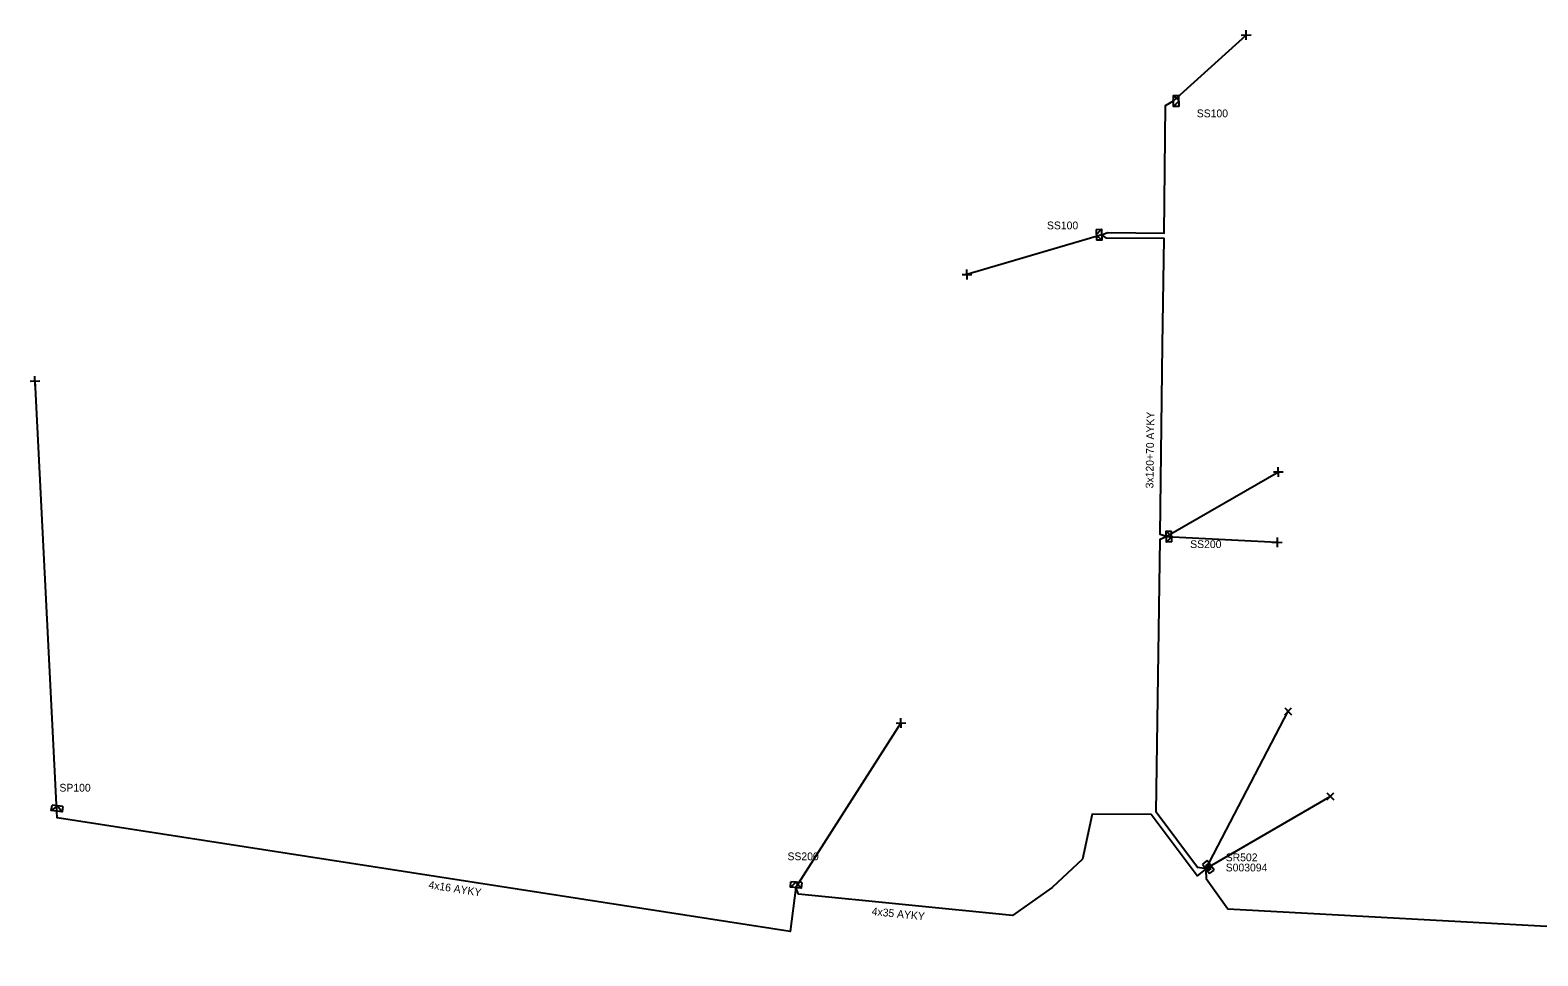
# Model space of a CAD drawing. Extents: x -762894 to -762498, y -1152897 to -1152214.
# Drawn here: x -762894 to -762701.3, y -1152896.3 to -1152777.9 of the extents above; entities that cross this region are included whole.
import ezdxf

# ---------------------------------------------------------------- set-up
doc = ezdxf.new("R2010")
doc.units = 0
for name, color, linetype in [('Vrstva 28', 7, 'Continuous'), ('Vrstva 29', 7, 'Continuous'), ('Vrstva 30', 7, 'Continuous'), ('Vrstva 31', 7, 'Continuous'), ('Vrstva 33', 7, 'Continuous'), ('Vrstva 34', 7, 'Continuous'), ('Vrstva 5', 7, 'Continuous'), ('Vrstva 52', 7, 'Continuous'), ('Vrstva 54', 7, 'Continuous'), ('Vrstva 59', 7, 'Continuous'), ('Vrstva 6', 7, 'Continuous')]:
    doc.layers.add(name, color=color, linetype=linetype)

msp = doc.modelspace()

# ---------------------------------------------------------------- linework, layer by layer
at = {"layer": 'Vrstva 28'}
for points in [[(-762743.546, -1152884.1), (-762744.145, -1152884.551)], [(-762742.643, -1152885.298), (-762743.546, -1152884.1)], [(-762744.145, -1152884.551), (-762743.242, -1152885.749)], [(-762743.466, -1152884.52), (-762743.768, -1152884.747)], [(-762743.768, -1152884.747), (-762743.32, -1152885.342)], [(-762743.475, -1152884.586), (-762743.702, -1152884.757)], [(-762743.702, -1152884.757), (-762743.311, -1152885.276)], [(-762743.485, -1152884.652), (-762743.635, -1152884.766)], [(-762743.635, -1152884.766), (-762743.301, -1152885.209)], [(-762743.494, -1152884.718), (-762743.569, -1152884.775)], [(-762743.569, -1152884.775), (-762743.292, -1152885.143)], [(-762743.279, -1152885.082), (-762743.507, -1152884.78)], [(-762743.217, -1152885.086), (-762743.494, -1152884.718)], [(-762743.15, -1152885.096), (-762743.485, -1152884.652)], [(-762743.084, -1152885.105), (-762743.475, -1152884.586)], [(-762743.018, -1152885.114), (-762743.466, -1152884.52)], [(-762743.32, -1152885.342), (-762743.018, -1152885.114)], [(-762743.311, -1152885.276), (-762743.084, -1152885.105)], [(-762743.301, -1152885.209), (-762743.15, -1152885.096)], [(-762743.292, -1152885.143), (-762743.217, -1152885.086)], [(-762743.242, -1152885.749), (-762742.643, -1152885.298)]]:
    msp.add_lwpolyline(points, dxfattribs=at)
at = {"layer": 'Vrstva 31'}
for points in [[(-762747.127, -1152787.621), (-762747.827, -1152787.633), (-762747.852, -1152786.233), (-762747.152, -1152786.221)], [(-762747.14, -1152786.921), (-762747.852, -1152786.233)], [(-762747.14, -1152786.921), (-762747.827, -1152787.633)], [(-762747.127, -1152787.621), (-762747.152, -1152786.221)], [(-762757.733, -1152803.359), (-762757.033, -1152803.347), (-762757.008, -1152804.747), (-762757.708, -1152804.759)], [(-762757.733, -1152803.359), (-762757.708, -1152804.759)], [(-762757.72, -1152804.059), (-762757.033, -1152803.347)], [(-762757.72, -1152804.059), (-762757.008, -1152804.747)], [(-762748.057, -1152843.341), (-762748.757, -1152843.353), (-762748.782, -1152841.953), (-762748.082, -1152841.941)], [(-762748.07, -1152842.641), (-762748.782, -1152841.953)], [(-762748.07, -1152842.641), (-762748.757, -1152843.353)], [(-762748.057, -1152843.341), (-762748.082, -1152841.941)], [(-762889.816, -1152877.185), (-762889.914, -1152877.878), (-762891.3, -1152877.683), (-762891.203, -1152876.99)], [(-762890.51, -1152877.087), (-762891.3, -1152877.683)], [(-762889.816, -1152877.185), (-762891.203, -1152876.99)], [(-762890.51, -1152877.087), (-762889.914, -1152877.878)], [(-762795.368, -1152886.914), (-762795.429, -1152887.611), (-762796.824, -1152887.489), (-762796.763, -1152886.792)], [(-762796.066, -1152886.853), (-762796.824, -1152887.489)], [(-762795.368, -1152886.914), (-762796.763, -1152886.792)], [(-762796.066, -1152886.853), (-762795.429, -1152887.611)]]:
    msp.add_lwpolyline(points, dxfattribs=at)
at = {"layer": 'Vrstva 34'}
for points in [[(-762738.549, -1152779.125), (-762738.571, -1152777.875)], [(-762739.185, -1152778.511), (-762737.935, -1152778.489)], [(-762774.239, -1152809.755), (-762774.261, -1152808.505)], [(-762774.875, -1152809.141), (-762773.625, -1152809.119)], [(-762893.369, -1152823.375), (-762893.391, -1152822.125)], [(-762894.005, -1152822.761), (-762892.755, -1152822.739)], [(-762734.429, -1152835.005), (-762734.451, -1152833.755)], [(-762735.065, -1152834.391), (-762733.815, -1152834.369)], [(-762735.185, -1152843.391), (-762733.935, -1152843.369)], [(-762734.549, -1152844.005), (-762734.571, -1152842.755)], [(-762733.632, -1152864.558), (-762732.748, -1152865.442)], [(-762733.632, -1152865.442), (-762732.748, -1152864.558)], [(-762783.315, -1152866.511), (-762782.065, -1152866.489)], [(-762782.679, -1152867.125), (-762782.701, -1152865.875)], [(-762728.252, -1152875.438), (-762727.368, -1152876.322)], [(-762728.252, -1152876.322), (-762727.368, -1152875.438)]]:
    msp.add_lwpolyline(points, dxfattribs=at)
at = {"layer": 'Vrstva 5'}
for points in [[(-762743.88, -1152885.12), (-762744.79, -1152884.97), (-762750.07, -1152877.92), (-762749.53, -1152843), (-762748.77, -1152842.65), (-762749.56, -1152842.38), (-762749.24, -1152818.11), (-762749.04, -1152804.54), (-762756.4, -1152804.49), (-762757.02, -1152804.05), (-762756.27, -1152803.74), (-762749.04, -1152803.83), (-762748.86, -1152787.5), (-762747.84, -1152786.93)], [(-762743.72, -1152885.33), (-762743.69, -1152886.39), (-762740.9, -1152890.25), (-762695.44, -1152892.73), (-762694.97, -1152892.29), (-762694.69, -1152892.8), (-762631.53, -1152896.28), (-762630.13, -1152859.24), (-762646.31, -1152858.66), (-762650.77, -1152870.2), (-762650.83, -1152869.13), (-762646.58, -1152858.04), (-762632.87, -1152850.42)], [(-762743.8, -1152885.22), (-762744.82, -1152886.04), (-762750.68, -1152878.19), (-762758.26, -1152878.14), (-762759.5, -1152883.91), (-762763.36, -1152887.55), (-762768.41, -1152891.1), (-762795.77, -1152888.39), (-762796.13, -1152887.55)]]:
    msp.add_lwpolyline(points, dxfattribs=at)
at = {"layer": 'Vrstva 52'}
msp.add_lwpolyline([(-762796.13, -1152887.55), (-762796.84, -1152893.18), (-762890.57, -1152878.63), (-762890.61, -1152877.79)], dxfattribs=at)
at = {"layer": 'Vrstva 59'}
for points in [[(-762747.84, -1152786.93), (-762738.56, -1152778.5)], [(-762757.02, -1152804.05), (-762774.25, -1152809.13)], [(-762890.61, -1152877.79), (-762893.38, -1152822.75)], [(-762748.77, -1152842.65), (-762734.44, -1152834.38)], [(-762748.77, -1152842.65), (-762734.56, -1152843.38)], [(-762796.13, -1152887.55), (-762782.69, -1152866.5)], [(-762743.24, -1152884.28), (-762733.19, -1152865)], [(-762742.93, -1152884.7), (-762727.81, -1152875.88)]]:
    msp.add_lwpolyline(points, dxfattribs=at)

# ---------------------------------------------------------------- texts
at = {"layer": 'Vrstva 29'}
msp.add_text('S003094', height=0.9943, dxfattribs=at).set_placement((-762741.17, -1152885.48))
at = {"layer": 'Vrstva 30'}
msp.add_text('SR502', height=0.9943, dxfattribs=at).set_placement((-762741.17, -1152884.18))
at = {"layer": 'Vrstva 33'}
for s, p in [('SS100', (-762744.87, -1152789.02)), ('SS100', (-762764.02, -1152803.35)), ('SS200', (-762745.71, -1152844.12)), ('SP100', (-762890.26, -1152875.27)), ('SS200', (-762797.19, -1152884.05))]:
    msp.add_text(s, height=0.9943, dxfattribs=at).set_placement(p)
at = {"layer": 'Vrstva 54'}
msp.add_text('4x16 AYKY', height=0.9943, rotation=351.17542, dxfattribs=at).set_placement((-762843.13, -1152887.64))
at = {"layer": 'Vrstva 6'}
for s, height, rotation, p in [('3x120+70 AYKY', 0.99429, 89.24108, (-762750.42, -1152836.49)), ('4x35 AYKY', 0.9943, 354.35052, (-762786.46, -1152891.06))]:
    msp.add_text(s, height=height, rotation=rotation, dxfattribs=at).set_placement(p)

doc.saveas('drawing.dxf')
